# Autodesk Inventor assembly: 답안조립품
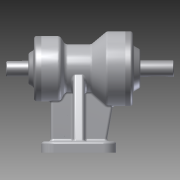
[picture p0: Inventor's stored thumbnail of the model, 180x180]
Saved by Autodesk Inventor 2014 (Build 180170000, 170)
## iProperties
Created: 2015-08
Part Number: 답안조립품
Document SubType Name: Assembly
Designer: SEC
Author: SEC
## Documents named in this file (10)
- C:\Users\SEC\Desktop\450805V1003\답안조립품.iam
- C:\Users\SEC\Desktop\450805V1003\축.ipt
- C:\Users\SEC\Desktop\450805V1003\베어링 6205.ipt
- C:\Users\SEC\Desktop\450805V1003\베어링 6203.ipt
- C:\Users\SEC\Desktop\450805V1003\본체.ipt
- C:\Users\SEC\Desktop\450805V1003\뒤커버.ipt
- C:\Users\SEC\Desktop\450805V1003\앞커버.ipt
- C:\Users\SEC\Desktop\450805V1003\오일실 .ipt
- 오일실 .ipt
- C:\Users\SEC\Desktop\450805V1003\M4x0.5.ipt
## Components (10 placed, 1 different names)
1. M4x0.5:1
2. M4x0.5:2
3. M4x0.5:3
4. M4x0.5:4
5. M4x0.5:5
6. M4x0.5:6
7. M4x0.5:7
8. M4x0.5:8
9. M4x0.5:9
10. M4x0.5:10
